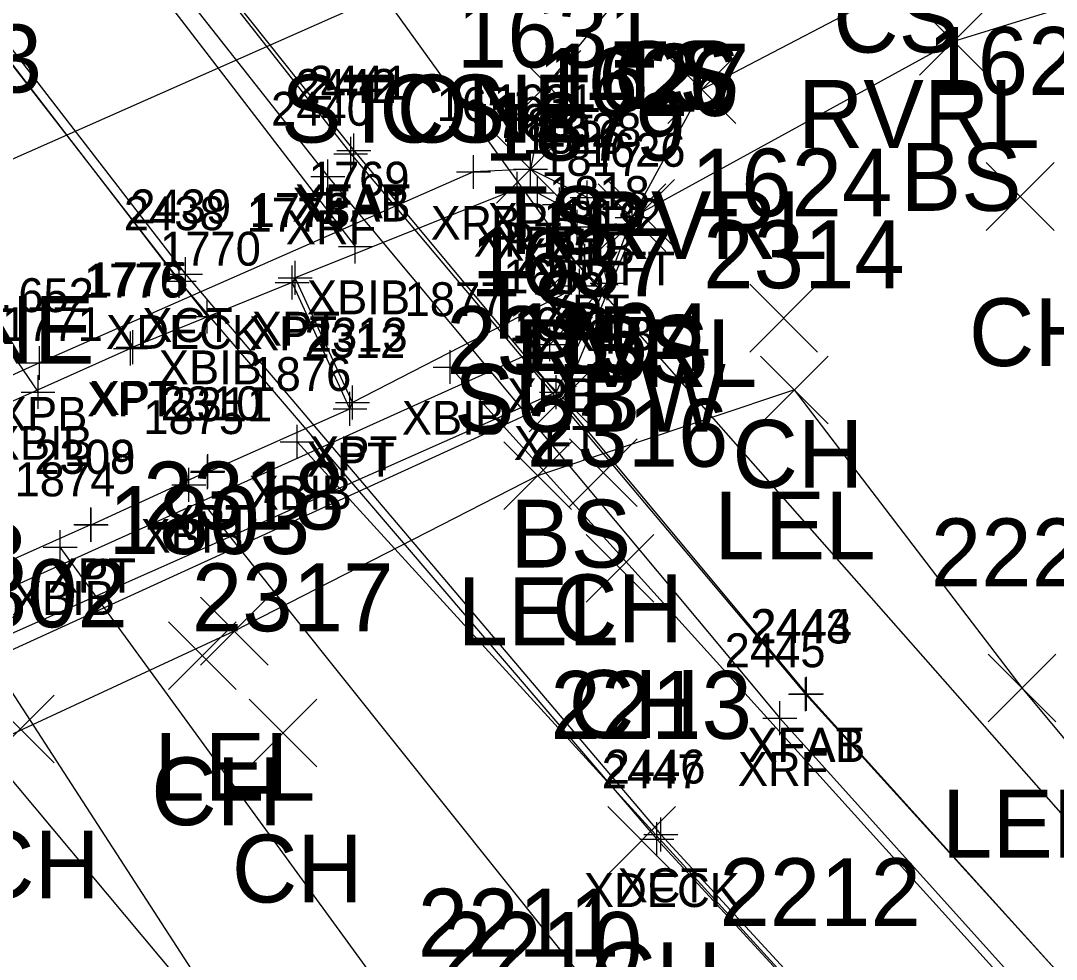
# Model space of a CAD drawing. Extents: x 1504228 to 1506103, y 437717 to 440106.
# Drawn here: x 1505234.96 to 1505265.52, y 438186.2 to 438213.89 of the extents above; entities that cross this region are included whole.
import ezdxf

# ---------------------------------------------------------------- set-up
doc = ezdxf.new("R2010")
doc.units = 0
for name, color, linetype in [('B_A', 7, 'Continuous'), ('B_I', 7, 'Continuous'), ('B_TIC', 7, 'Continuous'), ('BB', 7, 'Continuous'), ('BDC', 7, 'Continuous'), ('BELB', 7, 'Continuous'), ('BF', 7, 'Continuous'), ('BFT', 7, 'Continuous'), ('BR', 7, 'Continuous'), ('BSUBM', 7, 'Continuous'), ('L_A', 7, 'Continuous'), ('L_I', 7, 'Continuous'), ('L_TIC', 7, 'Continuous'), ('LARO', 7, 'Continuous'), ('LASF', 7, 'Continuous'), ('LAWE', 7, 'Continuous'), ('LELB', 7, 'Continuous'), ('U_A', 7, 'Continuous'), ('U_I', 7, 'Continuous'), ('U_TIC', 7, 'Continuous'), ('UW', 7, 'Continuous')]:
    doc.layers.add(name, color=color, linetype=linetype)

msp = doc.modelspace()

# ---------------------------------------------------------------- linework, layer by layer
at = {"layer": 'B_TIC'}
for p, q in [((1505244.699, 438209.964), (1505244.774, 438209.964)), ((1505244.788, 438210.059), (1505244.864, 438210.059)), ((1505250.004, 438209.507), (1505250.079, 438209.507)), ((1505244.021, 438209.29), (1505244.096, 438209.29)), ((1505248.32, 438209.426), (1505248.396, 438209.426)), ((1505249.608, 438208.929), (1505249.684, 438208.929)), ((1505249.608, 438208.929), (1505249.684, 438208.929)), ((1505250.215, 438208.808), (1505250.29, 438208.808)), ((1505251.677, 438208.67), (1505251.752, 438208.67)), ((1505251.677, 438208.67), (1505251.752, 438208.67)), ((1505250.862, 438208.466), (1505250.937, 438208.466)), ((1505253.002, 438208.079), (1505253.077, 438208.079)), ((1505251.383, 438207.811), (1505251.459, 438207.811)), ((1505244.834, 438207.228), (1505244.909, 438207.228)), ((1505251.611, 438206.805), (1505251.686, 438206.805)), ((1505239.826, 438206.409), (1505239.902, 438206.409)), ((1505239.633, 438206.209), (1505239.709, 438206.209)), ((1505242.973, 438206.167), (1505243.049, 438206.167)), ((1505243.059, 438206.301), (1505243.134, 438206.301)), ((1505252.266, 438206.145), (1505252.342, 438206.145)), ((1505252.266, 438206.145), (1505252.342, 438206.145)), ((1505251.455, 438206.067), (1505251.531, 438206.067)), ((1505240.463, 438205.162), (1505240.539, 438205.162)), ((1505238.274, 438204.261), (1505238.349, 438204.261)), ((1505250.573, 438204.342), (1505250.648, 438204.342)), ((1505238.199, 438204.221), (1505238.275, 438204.221)), ((1505235.515, 438203.792), (1505235.59, 438203.792)), ((1505247.635, 438203.673), (1505247.71, 438203.673)), ((1505235.471, 438202.936), (1505235.547, 438202.936)), ((1505250.766, 438202.931), (1505250.842, 438202.931)), ((1505244.678, 438202.443), (1505244.753, 438202.443)), ((1505244.751, 438202.628), (1505244.826, 438202.628)), ((1505244.751, 438202.628), (1505244.826, 438202.628)), ((1505243.115, 438201.465), (1505243.19, 438201.465)), ((1505240.48, 438200.603), (1505240.556, 438200.603)), ((1505240.471, 438200.574), (1505240.546, 438200.574)), ((1505239.923, 438200.195), (1505239.999, 438200.195)), ((1505237.029, 438199.027), (1505237.104, 438199.027)), ((1505237.043, 438199.021), (1505237.118, 438199.021)), ((1505236.124, 438198.358), (1505236.199, 438198.358)), ((1505258.121, 438194.019), (1505258.197, 438194.019)), ((1505258.153, 438194.034), (1505258.228, 438194.034)), ((1505257.364, 438193.318), (1505257.439, 438193.318)), ((1505253.736, 438189.745), (1505253.811, 438189.745)), ((1505253.853, 438189.887), (1505253.928, 438189.887))]:
    msp.add_line(p, q, dxfattribs=at)
for points in [[(1505244.695, 438209.464), (1505244.695, 438210.464)], [(1505244.785, 438209.559), (1505244.785, 438210.559)], [(1505244.017, 438208.79), (1505244.017, 438209.79)], [(1505244.195, 438209.964), (1505245.195, 438209.964)], [(1505244.285, 438210.059), (1505245.285, 438210.059)], [(1505248.317, 438208.926), (1505248.317, 438209.926)], [(1505250, 438209.006), (1505250, 438210.007)], [(1505249.5, 438209.507), (1505250.5, 438209.507)], [(1505243.517, 438209.29), (1505244.517, 438209.29)], [(1505247.817, 438209.426), (1505248.817, 438209.426)], [(1505249.605, 438208.429), (1505249.605, 438209.429)], [(1505249.605, 438208.429), (1505249.605, 438209.429)], [(1505250.211, 438208.308), (1505250.211, 438209.308)], [(1505251.673, 438208.17), (1505251.673, 438209.17)], [(1505251.673, 438208.17), (1505251.673, 438209.17)], [(1505249.105, 438208.929), (1505250.105, 438208.929)], [(1505249.105, 438208.929), (1505250.105, 438208.929)], [(1505250.858, 438207.966), (1505250.858, 438208.966)], [(1505249.711, 438208.808), (1505250.711, 438208.808)], [(1505251.173, 438208.67), (1505252.173, 438208.67)], [(1505251.173, 438208.67), (1505252.173, 438208.67)], [(1505252.998, 438207.579), (1505252.998, 438208.579)], [(1505250.358, 438208.466), (1505251.358, 438208.466)], [(1505251.38, 438207.311), (1505251.38, 438208.311)], [(1505252.498, 438208.079), (1505253.498, 438208.079)], [(1505244.83, 438206.728), (1505244.83, 438207.728)], [(1505250.88, 438207.811), (1505251.88, 438207.811)], [(1505244.33, 438207.228), (1505245.33, 438207.228)], [(1505251.607, 438206.305), (1505251.607, 438207.305)], [(1505239.63, 438205.709), (1505239.63, 438206.709)], [(1505239.823, 438205.909), (1505239.823, 438206.909)], [(1505243.055, 438205.801), (1505243.055, 438206.801)], [(1505251.107, 438206.805), (1505252.107, 438206.805)], [(1505239.323, 438206.409), (1505240.323, 438206.409)], [(1505242.97, 438205.667), (1505242.97, 438206.667)], [(1505251.452, 438205.567), (1505251.452, 438206.567)], [(1505252.263, 438205.645), (1505252.263, 438206.645)], [(1505252.263, 438205.645), (1505252.263, 438206.645)], [(1505239.13, 438206.209), (1505240.13, 438206.209)], [(1505242.47, 438206.167), (1505243.47, 438206.167)], [(1505242.555, 438206.301), (1505243.555, 438206.301)], [(1505251.763, 438206.145), (1505252.763, 438206.145)], [(1505251.763, 438206.145), (1505252.763, 438206.145)], [(1505250.952, 438206.067), (1505251.952, 438206.067)], [(1505240.46, 438204.662), (1505240.46, 438205.662)], [(1505239.96, 438205.162), (1505240.96, 438205.162)], [(1505238.196, 438203.721), (1505238.196, 438204.721)], [(1505238.27, 438203.761), (1505238.27, 438204.761)], [(1505250.569, 438203.842), (1505250.569, 438204.842)], [(1505235.511, 438203.292), (1505235.511, 438204.292)], [(1505237.77, 438204.261), (1505238.77, 438204.261)], [(1505250.069, 438204.342), (1505251.069, 438204.342)], [(1505237.696, 438204.221), (1505238.696, 438204.221)], [(1505247.631, 438203.173), (1505247.631, 438204.173)], [(1505235.011, 438203.792), (1505236.011, 438203.792)], [(1505247.131, 438203.673), (1505248.131, 438203.673)], [(1505235.468, 438202.436), (1505235.468, 438203.436)], [(1505250.763, 438202.431), (1505250.763, 438203.431)], [(1505244.747, 438202.128), (1505244.747, 438203.128)], [(1505244.747, 438202.128), (1505244.747, 438203.128)], [(1505234.968, 438202.936), (1505235.968, 438202.936)], [(1505244.674, 438201.943), (1505244.674, 438202.943)], [(1505250.263, 438202.931), (1505251.263, 438202.931)], [(1505244.174, 438202.443), (1505245.174, 438202.443)], [(1505244.247, 438202.628), (1505245.247, 438202.628)], [(1505244.247, 438202.628), (1505245.247, 438202.628)], [(1505243.111, 438200.965), (1505243.111, 438201.965)], [(1505242.611, 438201.465), (1505243.611, 438201.465)], [(1505240.467, 438200.074), (1505240.467, 438201.074)], [(1505240.477, 438200.103), (1505240.477, 438201.103)], [(1505239.92, 438199.695), (1505239.92, 438200.695)], [(1505239.977, 438200.603), (1505240.977, 438200.603)], [(1505239.967, 438200.574), (1505240.967, 438200.574)], [(1505239.42, 438200.195), (1505240.42, 438200.195)], [(1505237.025, 438198.527), (1505237.025, 438199.527)], [(1505237.039, 438198.521), (1505237.039, 438199.521)], [(1505236.12, 438197.858), (1505236.12, 438198.858)], [(1505236.525, 438199.027), (1505237.525, 438199.027)], [(1505236.539, 438199.021), (1505237.539, 438199.021)], [(1505235.62, 438198.358), (1505236.62, 438198.358)], [(1505258.118, 438193.519), (1505258.118, 438194.519)], [(1505258.149, 438193.534), (1505258.149, 438194.534)], [(1505257.618, 438194.019), (1505258.618, 438194.019)], [(1505257.649, 438194.034), (1505258.649, 438194.034)], [(1505257.36, 438192.818), (1505257.36, 438193.818)], [(1505256.86, 438193.318), (1505257.86, 438193.318)], [(1505253.732, 438189.245), (1505253.732, 438190.245)], [(1505253.849, 438189.387), (1505253.849, 438190.387)], [(1505253.232, 438189.745), (1505254.232, 438189.745)], [(1505253.349, 438189.887), (1505254.349, 438189.887)]]:
    msp.add_lwpolyline(points, dxfattribs=at)
at = {"layer": 'BB'}
for points in [[(1505216.867, 438243.586), (1505244.83, 438207.228)], [(1505212.21, 438241.584), (1505240.46, 438205.162)], [(1505209.818, 438240.537), (1505235.468, 438202.936)], [(1505279.36, 438168.588), (1505247.631, 438203.673)], [(1505274.859, 438166.697), (1505243.111, 438201.465)], [(1505269.01, 438163.806), (1505239.92, 438200.195)], [(1505263.198, 438161.205), (1505236.12, 438198.358)], [(1505257.379, 438159.077), (1505232.798, 438197.013)]]:
    msp.add_lwpolyline(points, dxfattribs=at)
at = {"layer": 'BDC'}
msp.add_lwpolyline([(1505211.925, 438243.921), (1505227.096, 438222.88), (1505239.823, 438206.409), (1505253.849, 438189.887), (1505268.071, 438174.436), (1505276.686, 438165.513)], dxfattribs=at)
at = {"layer": 'BELB'}
for points in [[(1505211.812, 438243.704), (1505226.972, 438222.631), (1505239.63, 438206.209), (1505253.732, 438189.745), (1505267.938, 438174.29), (1505276.516, 438165.316)], [(1505262.808, 438159.474), (1505244.884, 438179.311), (1505229.042, 438198.247), (1505213.306, 438219.16), (1505200.113, 438237.757)]]:
    msp.add_lwpolyline(points, dxfattribs=at)
at = {"layer": 'BF'}
for points in [[(1505211.925, 438243.921), (1505216.347, 438245.376), (1505218.618, 438242.78), (1505219.411, 438243.379), (1505231.883, 438226.243), (1505244.785, 438210.059), (1505258.149, 438194.034), (1505272.082, 438178.605), (1505279.641, 438170.867), (1505278.911, 438170.024), (1505281.091, 438167.856), (1505276.686, 438165.513)], [(1505219.325, 438243.288), (1505231.877, 438226.273), (1505244.695, 438209.964), (1505258.118, 438194.019), (1505272.126, 438178.595), (1505280.957, 438169.659)]]:
    msp.add_lwpolyline(points, dxfattribs=at)
at = {"layer": 'BFT'}
msp.add_lwpolyline([(1505252.998, 438208.079), (1505252.263, 438206.145), (1505250.763, 438202.931), (1505232.133, 438194.68), (1505231.606, 438194.296), (1505223.29, 438190.638), (1505216.076, 438187.39), (1505206.938, 438183.343), (1505196.92, 438178.938), (1505191.516, 438180.897), (1505192.342, 438183.974)], dxfattribs=at)
at = {"layer": 'BR'}
msp.add_lwpolyline([(1505218.618, 438242.78), (1505231.125, 438225.649), (1505244.017, 438209.29), (1505257.36, 438193.318), (1505271.307, 438177.817), (1505278.911, 438170.024)], dxfattribs=at)
at = {"layer": 'BSUBM'}
for points in [[(1505251.673, 438208.67), (1505250, 438209.507), (1505248.317, 438209.426), (1505235.511, 438203.792), (1505229.335, 438201.006), (1505222.013, 438197.676), (1505217.996, 438195.981), (1505203.564, 438189.562), (1505194.582, 438185.548), (1505193.788, 438184.98), (1505193.081, 438183.722)], [(1505249.605, 438208.929), (1505243.055, 438206.301), (1505242.97, 438206.167), (1505238.27, 438204.261), (1505238.196, 438204.221), (1505233.223, 438201.999), (1505233.186, 438201.942), (1505227.801, 438199.602), (1505227.776, 438199.546), (1505222.572, 438197.253), (1505222.418, 438197.249), (1505209.571, 438191.61), (1505197.655, 438186.296)], [(1505249.605, 438208.929), (1505250.211, 438208.808), (1505250.858, 438208.466), (1505251.38, 438207.811), (1505251.607, 438206.805), (1505251.452, 438206.067), (1505244.747, 438202.628)], [(1505251.673, 438208.67), (1505252.263, 438206.145), (1505250.569, 438204.342), (1505231.52, 438195.759), (1505231.146, 438195.559), (1505222.778, 438191.886), (1505216.199, 438188.925), (1505206.374, 438184.654), (1505196.87, 438180.394), (1505195.929, 438180.154), (1505194.33, 438180.389), (1505192.951, 438181.893), (1505193.081, 438183.722)], [(1505244.674, 438202.443), (1505242.97, 438206.167)], [(1505244.747, 438202.628), (1505243.055, 438206.301)], [(1505197.376, 438182.065), (1505223.277, 438192.822), (1505223.318, 438192.862), (1505226.793, 438194.369), (1505226.806, 438194.411), (1505230.178, 438195.942), (1505230.203, 438195.946), (1505233.647, 438197.525), (1505233.654, 438197.526), (1505237.025, 438199.027), (1505237.039, 438199.021), (1505240.477, 438200.603), (1505240.467, 438200.574), (1505244.674, 438202.443), (1505244.747, 438202.628)]]:
    msp.add_lwpolyline(points, dxfattribs=at)
at = {"layer": 'L_TIC'}
for points in [[(1505261.485, 438212.279), (1505263.485, 438214.279)], [(1505263.485, 438212.279), (1505261.485, 438214.279)], [(1505249.486, 438211.006), (1505251.486, 438213.006)], [(1505251.486, 438211.006), (1505249.486, 438213.006)], [(1505254.057, 438210.857), (1505256.057, 438212.857)], [(1505256.057, 438210.857), (1505254.057, 438212.857)], [(1505249, 438208.507), (1505251, 438210.507)], [(1505251, 438208.507), (1505249, 438210.507)], [(1505263.451, 438207.701), (1505265.451, 438209.701)], [(1505265.451, 438207.701), (1505263.451, 438209.701)], [(1505252.251, 438207.207), (1505254.251, 438209.207)], [(1505254.251, 438207.207), (1505252.251, 438209.207)], [(1505251.998, 438207.079), (1505253.998, 438209.079)], [(1505253.998, 438207.079), (1505251.998, 438209.079)], [(1505256.472, 438204.114), (1505258.472, 438206.114)], [(1505258.472, 438204.114), (1505256.472, 438206.114)], [(1505256.789, 438201.997), (1505258.789, 438203.997)], [(1505258.789, 438201.997), (1505256.789, 438203.997)], [(1505256.789, 438201.997), (1505258.789, 438203.997)], [(1505258.789, 438201.997), (1505256.789, 438203.997)], [(1505249.962, 438201.759), (1505251.962, 438203.759)], [(1505251.962, 438201.759), (1505249.962, 438203.759)], [(1505251.152, 438199.555), (1505253.152, 438201.555)], [(1505253.152, 438199.555), (1505251.152, 438201.555)], [(1505249.211, 438199.467), (1505251.211, 438201.467)], [(1505251.211, 438199.467), (1505249.211, 438201.467)], [(1505251.642, 438196.733), (1505253.642, 438198.733)], [(1505253.642, 438196.733), (1505251.642, 438198.733)], [(1505240.258, 438194.88), (1505242.258, 438196.88)], [(1505242.258, 438194.88), (1505240.258, 438196.88)], [(1505239.319, 438194.159), (1505241.319, 438196.159)], [(1505241.319, 438194.159), (1505239.319, 438196.159)], [(1505263.509, 438193.206), (1505265.509, 438195.206)], [(1505265.509, 438193.206), (1505263.509, 438195.206)], [(1505233.941, 438191.997), (1505235.941, 438193.997)], [(1505235.941, 438191.997), (1505233.941, 438193.997)], [(1505241.699, 438191.879), (1505243.699, 438193.879)], [(1505243.699, 438191.879), (1505241.699, 438193.879)], [(1505252.28, 438188.706), (1505254.28, 438190.706)], [(1505254.28, 438188.706), (1505252.28, 438190.706)]]:
    msp.add_lwpolyline(points, dxfattribs=at)
at = {"layer": 'LARO'}
for points in [[(1505257.789, 438202.997), (1505250.211, 438200.467), (1505241.258, 438195.88), (1505230.318, 438190.813), (1505221.077, 438187.488), (1505211.673, 438183.738), (1505205.073, 438180.218), (1505196.112, 438175.447), (1505190.999, 438172.732), (1505182.993, 438174.698), (1505180.265, 438174.662)], [(1505268.982, 438188.852), (1505264.509, 438194.206), (1505257.789, 438202.997)]]:
    msp.add_lwpolyline(points, dxfattribs=at)
at = {"layer": 'LASF'}
msp.add_lwpolyline([(1505231.536, 438240.553), (1505235.748, 438236.802), (1505232.624, 438230.462), (1505239.591, 438224.256), (1505247.096, 438215.294), (1505232.375, 438208.772), (1505219.716, 438203.952), (1505216.343, 438201.336), (1505195.139, 438190.329), (1505194.762, 438205.795)], dxfattribs=at)
at = {"layer": 'LAWE'}
msp.add_lwpolyline([(1505362.196, 438317.813), (1505351.384, 438297.395), (1505340.369, 438276.571), (1505330.226, 438263.864), (1505321.774, 438253.978), (1505312.194, 438244.278), (1505304.566, 438239.011), (1505294.241, 438232.21), (1505286.327, 438227.151), (1505272.047, 438220.927), (1505261.327, 438215.137), (1505255.057, 438211.857), (1505252.998, 438208.079)], dxfattribs=at)
at = {"layer": 'LELB'}
for points in [[(1505365.146, 438316.099), (1505353.966, 438296.236), (1505341.915, 438275.153), (1505332.016, 438262.134), (1505323.954, 438252.628), (1505313.563, 438242.629), (1505305.646, 438236.558), (1505295.746, 438229.78), (1505286.64, 438224.685), (1505273.677, 438216.738), (1505262.485, 438213.279), (1505253.251, 438208.207), (1505250.962, 438202.759), (1505231.919, 438194.06), (1505223.449, 438190.476), (1505215.829, 438187.003), (1505207.689, 438183.331), (1505196.859, 438178.456)], [(1505254.014, 438216.283), (1505250.486, 438212.006), (1505250, 438209.507)]]:
    msp.add_lwpolyline(points, dxfattribs=at)
at = {"layer": 'U_TIC'}
for points in [[(1505250.335, 438205.763), (1505252.335, 438207.763)], [(1505252.335, 438205.763), (1505250.335, 438207.763)]]:
    msp.add_lwpolyline(points, dxfattribs=at)
at = {"layer": 'UW'}
msp.add_lwpolyline([(1505283.181, 438170.638), (1505251.335, 438206.763), (1505225.076, 438243.18)], dxfattribs=at)

# ---------------------------------------------------------------- texts
at = {"layer": 'B_A'}
for s, p in [('XFAB', (1505242.967, 438207.964)), ('XFAT', (1505243.041, 438208.059)), ('XRF', (1505242.777, 438207.29)), ('XPB', (1505247.053, 438207.426)), ('XPB', (1505248.737, 438207.507)), ('XPT', (1505248.325, 438206.929)), ('XPT', (1505248.325, 438206.929)), ('XPT', (1505248.932, 438206.808)), ('XPB', (1505250.409, 438206.67)), ('XPB', (1505250.409, 438206.67)), ('XPT', (1505249.579, 438206.466)), ('XFT', (1505251.742, 438206.079)), ('XPT', (1505250.1, 438205.811)), ('XBIB', (1505243.401, 438205.228)), ('XPT', (1505250.328, 438204.805)), ('XDECK', (1505237.472, 438204.209)), ('XCT', (1505238.543, 438204.409)), ('XPT', (1505241.776, 438204.301)), ('XPT', (1505241.69, 438204.167)), ('XPT', (1505250.172, 438204.067)), ('XPB', (1505250.999, 438204.145)), ('XFT', (1505251.007, 438204.145)), ('XBIB', (1505239.03, 438203.162)), ('XPB', (1505249.306, 438202.342)), ('XPT', (1505236.916, 438202.221)), ('XPT', (1505236.991, 438202.261)), ('XPB', (1505234.248, 438201.792)), ('XBIB', (1505246.202, 438201.673)), ('XBIB', (1505234.039, 438200.936)), ('XFT', (1505249.507, 438200.931)), ('XPT', (1505243.468, 438200.628)), ('XPT', (1505243.468, 438200.628)), ('XPT', (1505243.395, 438200.443)), ('XBIB', (1505241.682, 438199.465)), ('XPT', (1505239.188, 438198.574)), ('XPT', (1505239.197, 438198.603)), ('XBIB', (1505238.491, 438198.195)), ('XPT', (1505235.746, 438197.027)), ('XPT', (1505235.76, 438197.021)), ('XBIB', (1505234.691, 438196.358)), ('XFAB', (1505256.389, 438192.019)), ('XFAT', (1505256.405, 438192.034)), ('XRF', (1505256.12, 438191.318)), ('XDECK', (1505251.575, 438187.745)), ('XCT', (1505252.57, 438187.887))]:
    msp.add_text(s, height=1, dxfattribs=at).set_placement(p)
at = {"layer": 'B_I'}
for s, p in [('2441', (1505243.439, 438211.559)), ('2442', (1505243.065, 438211.464)), ('1651', (1505247.23, 438210.926)), ('1631', (1505248.914, 438211.007)), ('2440', (1505242.344, 438210.79)), ('1768', (1505248.235, 438210.429)), ('1768', (1505248.235, 438210.429)), ('1815', (1505249.148, 438210.308)), ('1816', (1505249.768, 438209.966)), ('1628', (1505250.303, 438210.17)), ('1628', (1505250.303, 438210.17)), ('1626', (1505251.601, 438209.579)), ('1817', (1505250.317, 438209.311)), ('1769', (1505243.456, 438208.728)), ('1818', (1505250.544, 438208.305)), ('2439', (1505238.189, 438207.909)), ('2438', (1505238, 438207.709)), ('1774', (1505241.623, 438207.667)), ('1773', (1505241.709, 438207.801)), ('1819', (1505250.385, 438207.567)), ('1632', (1505250.893, 438207.645)), ('1632', (1505250.893, 438207.645)), ('1770', (1505239.07, 438206.662)), ('1776', (1505236.822, 438205.721)), ('1775', (1505236.924, 438205.761)), ('1635', (1505249.199, 438205.842)), ('1652', (1505234.141, 438205.292)), ('1877', (1505246.285, 438205.173)), ('1771', (1505234.405, 438204.436)), ('1636', (1505249.365, 438204.431)), ('2312', (1505243.328, 438203.943)), ('2313', (1505243.401, 438204.128)), ('2313', (1505243.401, 438204.128)), ('1876', (1505241.737, 438202.965)), ('2310', (1505239.087, 438202.103)), ('2311', (1505239.404, 438202.074)), ('1875', (1505238.573, 438201.695)), ('2308', (1505235.356, 438200.527)), ('2309', (1505235.366, 438200.521)), ('1874', (1505234.774, 438199.858)), ('2443', (1505256.488, 438195.519)), ('2444', (1505256.519, 438195.534)), ('2445', (1505255.731, 438194.818)), ('2446', (1505252.192, 438191.387)), ('2447', (1505252.102, 438191.245))]:
    msp.add_text(s, height=1, dxfattribs=at).set_placement(p)
at = {"layer": 'L_A'}
for s, p in [('CS', (1505258.933, 438212.948)), ('TS', (1505252.423, 438211.283)), ('CS', (1505252.455, 438211.283)), ('STONE', (1505242.64, 438210.294)), ('CS', (1505245.537, 438210.294)), ('RVRL', (1505257.894, 438210.137)), ('BS', (1505260.926, 438208.279)), ('TS', (1505248.896, 438207.006)), ('RVRL', (1505251.624, 438206.857)), ('TS', (1505248.41, 438204.507)), ('STONE', (1505227.918, 438203.772)), ('CH', (1505262.939, 438203.701)), ('BS', (1505251.692, 438203.207)), ('RVRL', (1505249.565, 438203.079)), ('CH', (1505255.96, 438200.114)), ('LEL', (1505255.427, 438197.997)), ('LEL', (1505255.427, 438197.997)), ('BS', (1505249.403, 438197.759)), ('CH', (1505250.641, 438195.555)), ('LEL', (1505247.848, 438195.467)), ('CH', (1505251.13, 438192.733)), ('LEL', (1505238.895, 438190.88)), ('CH', (1505238.808, 438190.159)), ('LEL', (1505262.147, 438189.206)), ('CH', (1505233.429, 438187.997)), ('CH', (1505241.187, 438187.879)), ('CH', (1505251.768, 438184.706))]:
    msp.add_text(s, height=2, dxfattribs=at).set_placement(p)
at = {"layer": 'L_I'}
for s, p in [('1631', (1505247.827, 438212.507)), ('1653', (1505229.634, 438211.772)), ('1622', (1505261.711, 438211.701)), ('1627', (1505250.511, 438211.207)), ('1626', (1505250.203, 438211.079)), ('1624', (1505254.732, 438208.114)), ('2314', (1505255.096, 438205.997)), ('2314', (1505255.096, 438205.997)), ('1637', (1505248.222, 438205.759)), ('2315', (1505247.518, 438203.467)), ('1804', (1505249.381, 438203.555)), ('2316', (1505249.894, 438200.733)), ('2318', (1505238.565, 438198.88)), ('1803', (1505237.548, 438198.159)), ('1638', (1505229.179, 438197.06)), ('2221', (1505261.816, 438197.206)), ('1802', (1505232.169, 438195.997)), ('2317', (1505240.006, 438195.879)), ('2213', (1505250.587, 438192.706)), ('2212', (1505255.575, 438187.183)), ('2211', (1505246.673, 438186.285)), ('2210', (1505247.355, 438185.597))]:
    msp.add_text(s, height=2, dxfattribs=at).set_placement(p)
at = {"layer": 'U_A'}
msp.add_text('SUBW', height=2, dxfattribs=at).set_placement((1505247.744, 438201.763))
at = {"layer": 'U_I'}
msp.add_text('1879', height=2, dxfattribs=at).set_placement((1505248.634, 438209.763))

doc.saveas('drawing.dxf')
